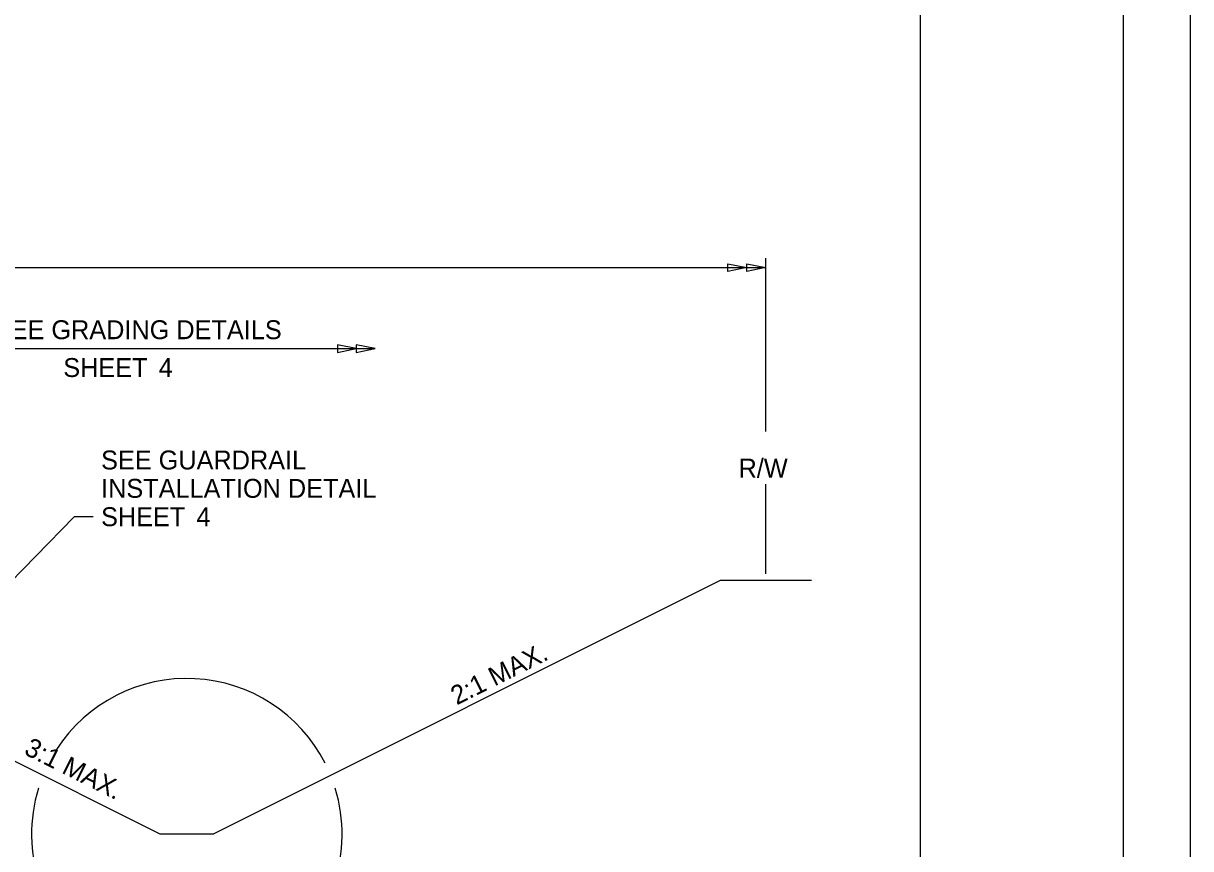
# Model space of a CAD drawing. Extents: x 0 to 170, y 0 to 110.
# Drawn here: x 126.77 to 170, y 24.46 to 55.01 of the extents above; entities that cross this region are included whole.
import ezdxf

# ---------------------------------------------------------------- set-up
doc = ezdxf.new("R2010")
doc.units = 0
for name, color, linetype in [('SH_Border', 7, 'Continuous'), ('SH_Cut_Line', 7, 'Continuous'), ('SH_Text', 7, 'Continuous'), ('XS_X_Ground_Line', 7, 'Continuous')]:
    doc.layers.add(name, color=color, linetype=linetype)

msp = doc.modelspace()

# ---------------------------------------------------------------- linework, layer by layer
at = {"layer": 'SH_Border'}
msp.add_line((160, 2.5), (160, 107.5), dxfattribs=at)
msp.add_lwpolyline([(7.5, 107.5), (167.5, 107.5), (167.5, 2.5), (7.5, 2.5)], close=True, dxfattribs=at)
at = {"layer": 'SH_Cut_Line'}
msp.add_lwpolyline([(0, 0), (170, 0), (170, 110), (0, 110)], close=True, dxfattribs=at)
at = {"layer": 'SH_Text'}
for p, q in [((154.266, 39.898), (154.266, 46.322)), ((99.95, 45.972), (154.266, 45.972)), ((122.45, 42.972), (139.801, 42.972)), ((154.266, 34.635), (154.266, 37.948)), ((125.751, 33.778), (128.656, 36.749)), ((129.356, 36.749), (128.656, 36.749)), ((152.575, 34.385), (133.825, 25.01)), ((122.45, 29.698), (131.825, 25.01)), ((131.825, 25.01), (133.825, 25.01))]:
    msp.add_line(p, q, dxfattribs=at)
for points in [[(152.866, 46.112), (153.566, 45.972), (152.866, 45.832)], [(153.566, 46.112), (154.266, 45.972), (153.566, 45.832)], [(138.401, 42.832), (139.101, 42.972), (138.401, 43.112)], [(139.101, 42.832), (139.801, 42.972), (139.101, 43.112)]]:
    msp.add_lwpolyline(points, close=True, dxfattribs=at)
for start, end in [(27.0865, 147.0577), (162.8779, 17.1221)]:
    msp.add_arc((132.825, 25.01), 5.75, start, end, dxfattribs=at)
at = {"layer": 'XS_X_Ground_Line'}
msp.add_line((155.957, 34.385), (152.575, 34.385), dxfattribs=at)

# ---------------------------------------------------------------- texts
at = {"layer": 'SH_Text'}
for s, p in [('SEE GRADING DETAILS', (125.676, 43.322)), ('SHEET ', (128.249, 41.922)), ('4', (131.782, 41.922)), ('SEE GUARDRAIL', (129.649, 38.499)), ('R/W', (153.258, 38.198)), ('INSTALLATION DETAIL', (129.649, 37.449)), ('SHEET ', (129.649, 36.399)), ('4', (133.182, 36.399))]:
    msp.add_text(s, height=0.7, dxfattribs=at).set_placement(p)
for s, rotation, p in [('2:1 MAX.', 26.5651, (142.822, 29.761)), ('3:1 MAX.', 333.4349, (126.76, 27.974))]:
    msp.add_text(s, height=0.7, rotation=rotation, dxfattribs=at).set_placement(p)

doc.saveas('drawing.dxf')
